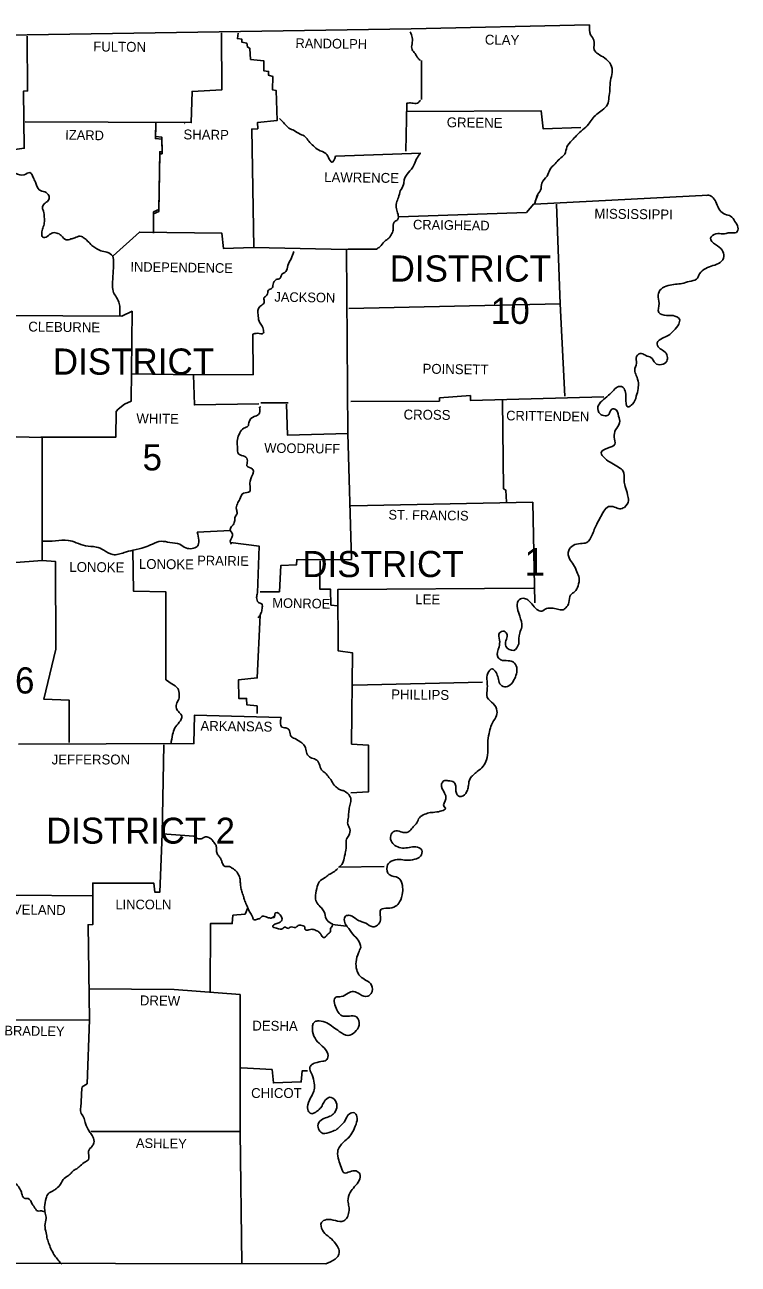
# Model space of a CAD drawing. Extents: x -17668 to 16999, y -17303 to 5867.
# Drawn here: x 2998 to 4708, y -10105 to -7133 of the extents above; entities that cross this region are included whole.
import ezdxf

# ---------------------------------------------------------------- set-up
doc = ezdxf.new("R2010")
doc.units = 0
for name, color, linetype in [('1', 7, 'Continuous'), ('2', 7, 'Continuous'), ('3', 7, 'Continuous')]:
    doc.layers.add(name, color=color, linetype=linetype)

msp = doc.modelspace()

# ---------------------------------------------------------------- linework, layer by layer
at = {"layer": '1'}
for p, q in [((4219.3, -7563.1), (4225.9, -7542.7)), ((4221, -7556.5), (4227.6, -7540.5)), ((3563.3, -8039.7), (3628.8, -8039.7)), ((3749.3, -9152.5), (3859.4, -9150.8))]:
    msp.add_line(p, q, dxfattribs=at)
for points in [[(1332.2, -7158.5), (2222.1, -7159.1), (3003, -7157.4), (3924.3, -7143.1), (4351.4, -7133.2)], [(3003, -7160.7), (3004.1, -7291.7), (2994.8, -7292.3), (2996.4, -7429.3), (2957.9, -7434.8), (2961.2, -7471.7), (2974.4, -7488.8), (2973.3, -7532.2), (2898.5, -7535), (2895.7, -7602.1), (2827.5, -7604.3), (2824.2, -7685.8), (2828, -7692.4), (2829.7, -7822.3), (2947.5, -7830), (2945.8, -8120), (3039.4, -8122.8), (3039.4, -8417.8), (2965.6, -8423.3), (2960.1, -8488.2), (2836.3, -8488.8)], [(3469.2, -7152.5), (3470.3, -7289), (3398.7, -7292.8), (3396.5, -7367.7), (2998.6, -7365.5)], [(3508.8, -7153), (3507.2, -7166.3), (3518.2, -7167.9), (3517.6, -7174.5), (3530.3, -7177.3), (3531.4, -7186.1), (3537.4, -7189.9), (3539.1, -7216.3), (3570.5, -7219.6), (3570.5, -7243.3), (3582, -7245), (3582, -7254.3), (3591.9, -7257.1), (3591.4, -7289), (3600.2, -7290.6), (3602.4, -7362.7), (3555.6, -7367.1), (3556.1, -7382.5), (3541.8, -7383.1), (3546.8, -7667.1), (3768.6, -7672), (3772.4, -8113.4), (3627.7, -8117.3), (3624.9, -8043)], [(3948.5, -7219.1), (3948.5, -7312.1)], [(3911.1, -7435.9), (3913.9, -7320.9), (3913.9, -7341.3), (4235.8, -7339.6), (4240.2, -7382.5), (4331, -7379.2)], [(3311.8, -7369.3), (3310.7, -7401.3), (3326.1, -7402.4), (3326.6, -7437.6), (3321.1, -7437.6), (3318.9, -7576.3), (3306.3, -7581.8), (3306.3, -7628)], [(3311.8, -7374.3), (3310.7, -7406.2), (3326.1, -7407.3), (3326.6, -7442.5), (3321.1, -7442.5), (3318.9, -7581.2), (3306.3, -7586.7), (3306.3, -7633)], [(3380.6, -7370.4), (3381.1, -7369.9)], [(3742.7, -7448), (3946.9, -7440.9)], [(4219.3, -7563.1), (4637, -7541.6)], [(3894.6, -7593.3), (4200.1, -7583.4), (4218.2, -7562.5)], [(4272.2, -7563.6), (4281.5, -7801.9), (4292.5, -8023.7)], [(3209.4, -7686.9), (3272.2, -7630.2), (3470.3, -7633), (3474.1, -7669.8), (3546.2, -7667.1)], [(3840.7, -7670.9), (3773.5, -7670.9), (3768.6, -7672)], [(4281.5, -7801.9), (3774.6, -7813.5)], [(2947.5, -7830), (3230.3, -7831.6), (3254.6, -7820.1), (3252.9, -8035.3), (3236.4, -8042.4), (3221.5, -8055.1), (3216.6, -8060), (3216, -8121.7), (3036.1, -8121.7)], [(3544, -7875.1), (3545.1, -7972), (3402, -7972.5), (3255.1, -7969.8)], [(3402, -7972.5), (3404.2, -8044.6), (3558.9, -8041.9)], [(3779, -8036.4), (3991.5, -8035.3), (3992, -8027.6), (4065.8, -8022.1), (4065.8, -8033.6), (4386.1, -8024.8)], [(3563.3, -8049), (3560.5, -8049.6)], [(4142.8, -8033.6), (4145.6, -8245.5), (4150.5, -8248.8), (4152.2, -8277.4)], [(3772.4, -8113.4), (3780.7, -8415), (3649.7, -8415.6), (3649.2, -8427.7), (3611.2, -8429.9), (3607.9, -8492.6), (3561.6, -8492.6)], [(3779, -8286.8), (4216, -8278)], [(4216, -8278), (4220.4, -8519)], [(3410.9, -8349.5), (3490.7, -8345.7)], [(3490.7, -8374.3), (3559.4, -8383.1), (3555.6, -8495.4)], [(3256.8, -8392.4), (3257.9, -8491), (3335.5, -8492.6), (3336, -8703.9)], [(3039.4, -8417.8), (3071.3, -8420), (3071.8, -8630.2), (3043.2, -8749.6), (3104.3, -8752.4), (3103.8, -8853.6)], [(3705.8, -8418.3), (3705.3, -8486.6), (3730.6, -8486.6), (3731.7, -8524.5), (3747.7, -8526.2)], [(3779, -8974.7), (3822, -8972), (3821.4, -8860.2), (3781.2, -8857.5), (3783.4, -8639), (3748.8, -8634), (3747.7, -8487.1), (4217.1, -8483.8)], [(3561.6, -8548.2), (3555, -8699), (3509.9, -8703.9), (3511, -8748.5), (3529.2, -8748), (3529.7, -8763.4), (3554.5, -8766.1), (3555, -8784.3)], [(3784.5, -8716.6), (4094.9, -8708.9)], [(3612.3, -8794.2), (3404.2, -8788.7), (3403.1, -8856.4), (2982.1, -8858)], [(3331, -8859.7), (3326.6, -9072.7), (3403.1, -9078.7)], [(3326.6, -9072.7), (3321.7, -9212.5), (3309, -9212.5), (3306.8, -9191), (3160.4, -9191), (3160.4, -9221.8)], [(2964.5, -9220.2), (3159.3, -9221.3)], [(3160.4, -9221.3), (3161, -9290.1), (3149.4, -9290.6), (3152.7, -9519)], [(3532.5, -9250.4), (3525.9, -9265.3), (3496.7, -9268.1), (3495.1, -9287.9), (3442.8, -9287.9), (3442.2, -9452.4)], [(3594.1, -9274.7), (3595.8, -9273), (3597.4, -9271.4), (3597.4, -9271.4)], [(3151.1, -9444.2), (3355.3, -9445.8), (3513.8, -9457.9)], [(3513.8, -9457.9), (3513.8, -9787), (3518.2, -10103.5)], [(2904, -9519.6), (3152.7, -9519)], [(3152.7, -9519), (3147.2, -9672), (3135.1, -9679.7)], [(1700.9, -9655), (1702, -10100.2), (3719, -10103.5)], [(3516.5, -9633.5), (3590.3, -9637.9), (3593.6, -9669.8), (3660.2, -9667.6), (3662.9, -9640.6), (3675.6, -9640.6)], [(3156, -9786.5), (3513.8, -9786.5)]]:
    msp.add_lwpolyline(points, dxfattribs=at)
for points in [[(3921.6, -7150.3), (3926.5, -7164.1), (3926, -7178.9), (3926, -7192.7), (3933.1, -7202), (3940.3, -7213.6), (3945.8, -7218.5)], [(4351.4, -7133.2), (4354.2, -7157.4), (4361.9, -7170.1), (4363, -7193.2), (4372.3, -7203.1), (4388.3, -7213), (4402.6, -7229), (4405.9, -7247.7), (4401.5, -7267), (4400.4, -7288.4), (4398.2, -7307.1), (4394.9, -7324.2), (4381.7, -7338), (4369, -7347.9), (4357.5, -7359.4), (4349.2, -7371.5), (4334.9, -7384.7), (4320.6, -7398.5), (4309, -7410.6), (4297.5, -7426), (4292, -7443.1), (4279.3, -7455.2), (4269.4, -7466.2), (4256.2, -7481.1), (4249.6, -7495.9), (4236.9, -7513), (4234.2, -7529.5), (4225.9, -7542.7), (4225.4, -7544.9)], [(3946.3, -7313.7), (3939.2, -7320.9), (3925.4, -7320.9), (3913.9, -7320.9)], [(3608.4, -7357.8), (3620.5, -7370.4), (3631, -7380.9), (3643.1, -7386.9), (3657.4, -7395.2), (3670.1, -7401.8), (3678.3, -7412.3), (3689.9, -7423.8), (3701.4, -7433.2), (3719.6, -7442), (3725.7, -7451.3), (3733.9, -7462.9), (3742.7, -7448)], [(3945.2, -7441.4), (3937, -7454.6), (3930.4, -7470), (3917.2, -7487.7), (3907.3, -7504.7), (3905.6, -7516.3), (3897.9, -7531.7), (3893.5, -7547.1), (3888.6, -7560.3), (3888.6, -7574.1), (3892.4, -7587.8), (3891.3, -7600.5), (3883.1, -7606.5), (3880.9, -7622.5), (3877.6, -7633.5), (3870.4, -7644.5), (3859.9, -7652.8), (3848.9, -7665.4), (3840.7, -7670.9)], [(2974.4, -7488.8), (2996.4, -7492.6), (3009.6, -7487.7), (3019, -7502), (3024, -7513), (3032.2, -7528.9), (3045.4, -7533.9), (3055.3, -7542.7), (3055.3, -7552.1), (3046.5, -7560.9), (3039.9, -7569.7), (3042.1, -7580.1), (3044.3, -7594.4), (3044.3, -7608.2), (3041, -7620.8), (3038.3, -7632.4), (3041, -7642.3), (3051.5, -7640.7), (3062.5, -7632.4), (3074, -7632.4), (3085, -7638.5), (3096.6, -7648.9), (3108.2, -7646.7), (3117.5, -7644), (3130.7, -7640.1), (3140.1, -7645.1), (3148.3, -7651.7), (3158.2, -7662.1), (3167.6, -7668.7), (3179.7, -7674.8), (3194.6, -7678.6), (3208.3, -7688), (3210.5, -7703.9), (3210, -7717.7), (3208.9, -7734.8), (3207.8, -7753.5), (3209.4, -7771.6), (3215.5, -7783.8), (3223.2, -7798.1), (3225.4, -7811.3), (3224.8, -7832.2)], [(4631, -7542.1), (4637, -7541.6), (4655.8, -7561.4), (4664, -7577.9), (4676.1, -7587.3), (4689.9, -7592.2), (4700.3, -7604.9), (4707.5, -7618.6), (4703.6, -7630.8), (4688.2, -7631.9), (4671.2, -7634.6), (4654.7, -7634.1), (4641.4, -7645.1), (4653.5, -7659.9), (4669.5, -7673.7), (4673.9, -7688.5), (4665.1, -7702.8), (4647.5, -7710.6), (4630.4, -7717.2), (4615, -7730.4), (4607.9, -7743), (4590.8, -7748.5), (4573.2, -7753.5), (4557.8, -7755.1), (4540.2, -7758.4), (4523.1, -7766.7), (4516, -7781), (4518.2, -7801.4), (4517.6, -7822.8), (4535.8, -7830), (4551.7, -7830.5), (4567.1, -7838.8), (4565.5, -7850.9), (4553.9, -7866.3), (4540.2, -7878.4), (4526.4, -7884.5), (4513.8, -7896), (4518.2, -7907.6), (4529.7, -7915.3), (4538, -7927.9), (4536.9, -7939.5), (4523.7, -7947.8), (4509.4, -7944.5), (4498.9, -7930.7), (4486.8, -7926.3), (4476.3, -7921.3), (4464.2, -7928.5), (4464.2, -7944.5), (4459.8, -7961.5), (4463.7, -7974.2), (4468.6, -7991.8), (4468.1, -8005), (4463.7, -8023.7), (4454.3, -8043), (4443.3, -8049), (4438.9, -8028.1), (4436.7, -8011), (4430.1, -8001.1), (4421.3, -8000.6), (4409.7, -8008.8), (4397.1, -8021.5), (4381.1, -8035.3), (4371.8, -8049), (4376.7, -8066.1), (4388.8, -8070.5), (4398.2, -8067.2), (4403.1, -8056.2), (4412.5, -8054.5), (4421.3, -8071.6)], [(3642.5, -7677), (3635.9, -7694), (3628.2, -7710.6), (3623.3, -7724.9), (3612.8, -7733.1), (3609.5, -7740.8), (3600.2, -7744.1), (3593, -7755.1), (3589.7, -7765), (3582, -7769.4), (3578.2, -7781.5), (3571, -7788.2), (3571.6, -7799.2), (3563.3, -7806.9), (3556.7, -7815.7), (3556.7, -7827.8), (3559.4, -7843.7), (3564.9, -7853.1), (3569.9, -7865.2), (3569.4, -7872.9), (3555.6, -7872.9), (3544, -7875.1)], [(3560.5, -8049.6), (3557.8, -8067.7), (3547.3, -8072.7), (3535.2, -8084.8), (3532.5, -8095.8), (3522.6, -8100.2), (3513.2, -8111.8), (3507.2, -8127.7), (3507.2, -8144.2), (3511, -8162.9), (3524.8, -8167.9), (3531.4, -8178.9), (3530.3, -8190.5), (3543.5, -8198.2), (3545.7, -8204.8), (3543.5, -8211.9), (3537.4, -8232.3), (3538, -8246), (3536.9, -8252.1), (3522, -8256), (3513.2, -8270.8), (3507.2, -8281.3), (3505, -8295), (3506.6, -8304.9), (3502.2, -8312.6), (3500.6, -8324.2), (3495.1, -8334.1), (3490.1, -8343.5), (3495.6, -8354.5), (3494, -8362.2), (3490.7, -8374.3), (3493.4, -8378.1)], [(4421.3, -8071.6), (4423.5, -8087.5), (4414.1, -8104.6), (4410.8, -8121.7), (4412.5, -8138.7), (4394.9, -8148.1), (4379.5, -8159.1), (4388.3, -8172.3), (4404.8, -8184.4), (4421.3, -8193.8), (4431.8, -8203.1), (4434.5, -8225.7), (4437.3, -8240), (4442.8, -8259.8), (4445, -8273.6), (4435.1, -8290.1), (4423.5, -8293.4), (4411.4, -8289.5), (4397.1, -8288.4), (4385.5, -8299.4), (4377.3, -8314.8), (4369, -8330.3), (4363, -8343.5), (4356.9, -8357.8), (4344.8, -8374.3), (4329.9, -8377), (4312.3, -8381.4), (4301.9, -8393.5), (4303.5, -8413.9), (4313.4, -8427.7), (4321.1, -8444.7), (4326.6, -8459.6), (4323.9, -8478.3), (4316.2, -8492.1), (4306.3, -8500.3), (4301.9, -8517.9), (4294.7, -8531.1), (4288.1, -8535.5), (4274.9, -8534.4), (4260.6, -8531.7), (4248.5, -8532.8), (4236.9, -8538.8), (4225.4, -8535), (4213.3, -8521.8), (4203.4, -8511.9), (4192.4, -8508), (4180.8, -8514.1), (4178.6, -8532.2), (4184.1, -8550.9), (4189.1, -8576.3), (4184.1, -8591.7), (4182.4, -8617)], [(3040.5, -8371.5), (3071.3, -8370.4), (3101.6, -8369.3), (3120.8, -8374.8), (3142.8, -8382), (3168.7, -8385.3), (3186.9, -8392.4), (3208.3, -8403.4), (3235.8, -8398.5), (3257.3, -8393), (3285.4, -8385.8), (3303.5, -8378.1), (3324.4, -8371.5), (3345.4, -8374.3), (3369, -8378.7), (3383.9, -8387.5), (3410.9, -8383.6), (3410.9, -8349.5)], [(3555.6, -8495.4), (3553.4, -8506.4), (3557.8, -8517.9), (3565.5, -8521.8), (3566.6, -8532.8), (3563.8, -8543.8), (3561.6, -8548.2), (3556.7, -8554.8)], [(4182.4, -8617), (4169.8, -8632.9), (4151.1, -8623), (4151.1, -8609.8), (4153.8, -8596.1), (4147.2, -8587.3), (4135.7, -8591.1), (4135.7, -8608.2), (4134.6, -8624.7), (4131.3, -8648.4), (4139, -8655.5), (4156.6, -8657.7), (4169.2, -8661), (4176.9, -8673.7), (4176.4, -8689.1), (4170.3, -8703.9), (4161.5, -8716), (4147.8, -8720.5), (4136.8, -8713.3), (4132.4, -8699), (4127.4, -8686.3), (4118.1, -8677), (4108.1, -8687.4), (4105.9, -8706.7), (4106.5, -8723.2), (4106.5, -8745.8), (4120.8, -8760.6), (4129.6, -8777.7), (4126.9, -8793.1), (4116.4, -8811.3), (4112, -8827.2), (4107.6, -8848.7), (4108.1, -8872.3), (4104.3, -8895.5), (4096.6, -8910.9), (4082.3, -8923.5), (4072.9, -8931.8), (4065.2, -8940), (4061.4, -8956.6), (4058.6, -8968.1), (4048.2, -8981.9), (4039.9, -8983), (4033.3, -8977.5), (4031.1, -8968.1), (4031.1, -8958.8), (4026.7, -8949.4), (4012.9, -8945.5), (4001.9, -8946.1), (3997, -8953.8), (4004.1, -8975.3), (4006.9, -8989), (4003, -9007.7), (4005.2, -9009.9), (3985.4, -9020.4), (3969.5, -9022), (3956.3, -9025.9), (3943.6, -9034.2), (3937.5, -9046.3), (3928.7, -9056.2), (3921, -9065.5), (3910.6, -9069.9), (3899, -9067.7), (3883.6, -9066.1), (3874.8, -9077.1), (3877.6, -9093), (3888, -9102.4), (3903.4, -9106.8), (3919.4, -9105.7), (3934.8, -9104), (3949.1, -9111.8), (3946.3, -9126.6), (3932.6, -9133.8), (3912.2, -9136), (3895.7, -9134.3), (3875.9, -9138.7), (3866, -9151.4), (3871.5, -9170.6), (3893, -9178.3), (3902.9, -9196.5), (3903.4, -9213.6), (3896.3, -9236.1), (3886.4, -9246.6), (3867.1, -9251), (3852.2, -9253.7), (3850, -9279.1), (3843.4, -9291.7), (3831.9, -9295.6), (3815.4, -9287.3), (3805.5, -9283.5), (3793.3, -9278), (3777.9, -9268.6), (3766.4, -9270.3), (3769.7, -9294.5), (3770.8, -9295.6), (3784, -9313.7), (3797.2, -9328), (3803.3, -9345.1)], [(3336, -8703.9), (3349.8, -8713.3), (3364.1, -8724.3), (3367.9, -8739.2), (3366.8, -8749.6), (3362.4, -8758.4), (3361.3, -8772.2), (3367.9, -8782.1), (3374, -8790.3), (3367.9, -8805.2), (3357.5, -8819), (3352, -8834.4), (3348.1, -8857.5)], [(3612.3, -8794.2), (3613.9, -8816.8), (3627.1, -8820.1), (3632.6, -8826.1), (3635.4, -8838.8), (3644.8, -8844.3), (3657.4, -8852), (3665.1, -8857.5), (3670.6, -8866.3), (3673.9, -8880.6), (3682.7, -8890), (3694.8, -8894.4), (3703.6, -8904.8), (3709.1, -8919.7), (3717.9, -8926.3), (3726.8, -8937.8), (3731.2, -8942.8), (3738.9, -8956), (3746.6, -8962.6), (3752.1, -8966.5), (3760.9, -8969.2), (3771.9, -8976.4), (3779, -8987.4), (3779, -8995.6), (3776.3, -9008.3), (3774.1, -9021.5), (3773, -9036.4), (3771.9, -9049.6), (3776.8, -9060.6), (3774.1, -9077.1), (3768.6, -9085.9), (3768, -9098), (3766.4, -9116.2), (3764.2, -9126.6), (3759.2, -9143.7), (3752.1, -9152.5)], [(3403.1, -9078.7), (3411.4, -9084.2), (3423, -9083.7), (3430.7, -9080.4), (3436.7, -9080.9), (3445, -9085.9), (3450.5, -9092.5), (3454.3, -9097.4), (3457.1, -9105.1), (3457.1, -9112.3), (3459.8, -9122.2), (3463.1, -9126.1), (3467.5, -9133.2), (3470.3, -9139.8), (3471.9, -9144.2), (3478, -9151.4), (3483.5, -9150.8), (3488.5, -9151.4), (3495.1, -9155.2), (3505, -9162.9), (3506.6, -9165.1), (3513.2, -9179.4), (3514.3, -9188.3), (3515.4, -9199.8), (3517.6, -9210.8), (3522, -9222.9), (3524.2, -9231.2), (3529.2, -9242.7), (3532.5, -9250.4), (3536.9, -9260.3), (3543.5, -9271.4), (3546.2, -9278), (3555.6, -9277.4), (3562.2, -9274.7), (3567.2, -9270.3), (3573.2, -9270.8), (3579.8, -9273), (3588.6, -9274.7), (3594.1, -9271.4), (3596.9, -9269.2), (3597.4, -9264.2), (3602.4, -9261.5), (3607.9, -9265.3), (3613.9, -9274.1), (3613.9, -9279.6), (3611.7, -9282.9), (3604.6, -9287.3), (3594.7, -9290.6), (3591.9, -9294.5), (3601.3, -9298.9), (3616.1, -9300), (3620, -9296.7), (3629.9, -9299.4), (3633.7, -9296.7), (3647, -9297.2), (3653, -9292.8), (3665.1, -9293.4), (3669, -9296.1), (3669, -9301.1), (3678.9, -9303.3), (3686, -9301.6), (3695.4, -9304.4), (3703.6, -9308.8), (3708, -9314.8), (3713.5, -9321.4), (3718.5, -9319.8), (3722.4, -9314.8), (3730.6, -9306), (3730.6, -9300.5), (3732.8, -9296.7), (3735.6, -9291.2)], [(3748.2, -9155.8), (3736.7, -9165.1), (3726.8, -9170.6), (3716.3, -9178.3), (3703.6, -9187.7), (3697.6, -9203.7), (3694.3, -9225.7), (3698.7, -9238.9), (3708.6, -9250.4), (3715.2, -9259.8), (3720.1, -9276.3), (3732.3, -9287.9), (3736.1, -9289.5)], [(3803.3, -9345.1), (3797.7, -9357.8), (3791.7, -9379.8), (3793.3, -9398.5), (3801.6, -9414.4), (3814.8, -9423.3), (3829.1, -9435.9), (3828, -9455.2), (3819.8, -9462.3), (3800.5, -9457.4), (3785.6, -9450.8), (3773, -9454.6), (3755.9, -9462.9), (3743.3, -9464.5), (3743.8, -9490.9), (3760.9, -9509.7), (3775.7, -9509.7), (3792.8, -9511.9), (3798.9, -9531.7), (3788.9, -9548.2), (3772.4, -9556.4), (3751.5, -9546.5), (3736.7, -9536.1), (3721.8, -9526.2), (3703.1, -9521.2), (3692.6, -9523.4), (3687.7, -9546.5), (3696.5, -9567.4), (3710.8, -9581.8), (3724, -9600.5), (3721.8, -9614.2), (3711.9, -9618.1), (3694.3, -9621.9), (3683.8, -9627.4), (3681.1, -9631.8), (3686.6, -9650.6), (3691.5, -9670.9), (3691.5, -9686.3), (3685.5, -9700.6), (3676.1, -9722.6), (3677.2, -9737), (3683.8, -9743.6), (3692.1, -9741.4), (3703.1, -9733.7), (3710.2, -9724.8), (3716.3, -9713.8), (3727.9, -9704.5), (3742.2, -9712.7), (3745.5, -9729.8), (3737.2, -9744.7), (3725.7, -9751.3), (3711.3, -9756.8), (3700.9, -9768.9), (3703.6, -9783.2), (3711.9, -9790.9), (3732.3, -9787), (3746, -9781), (3753.7, -9773.3), (3763.1, -9763.9), (3768, -9754.6), (3775.2, -9744.7), (3787.8, -9741.9), (3793.9, -9750.2), (3791.7, -9768.9), (3784, -9786.5), (3773.5, -9801.3), (3762, -9811.8), (3747.7, -9834.4), (3750.4, -9855.3), (3755.9, -9872.3), (3763.6, -9885.6), (3776.8, -9882.8), (3791.7, -9881.1), (3800.5, -9888.3), (3799.4, -9903.7), (3788.4, -9918.6), (3777.9, -9932.9), (3772.4, -9952.7), (3774.6, -9966.5), (3774.6, -9979.1), (3770.2, -9992.9), (3762.5, -10000.6), (3742.2, -10000), (3720.7, -9997.8), (3709.1, -10004.4), (3711.3, -10023.1), (3724, -10036.9), (3732.8, -10044.1), (3745.5, -10059.5), (3751, -10072.1), (3749.3, -10083.1), (3741.6, -10092.5), (3719, -10103.5)], [(3135.1, -9679.7), (3133.5, -9696.8), (3132.9, -9712.7), (3131.8, -9728.2), (3131.8, -9739.7), (3138.4, -9752.4), (3142.3, -9764.5), (3146.1, -9774.9), (3153.8, -9788.7), (3161, -9799.1), (3163.2, -9814), (3158.8, -9821.7), (3150.5, -9833.3), (3150, -9854.2), (3140.1, -9860.8), (3127.4, -9871.8), (3120.3, -9876.7), (3112.6, -9881.7), (3104.3, -9890.5), (3092.2, -9898.8), (3083.4, -9912.5), (3073.5, -9923), (3065.2, -9928.5), (3053.7, -9935.6), (3048.7, -9946.6), (3044.9, -9967), (3046.5, -9981.9), (3048.7, -9995.1), (3046, -10011.6), (3048.7, -10029.7), (3051.5, -10044.1), (3055.9, -10056.7), (3061.9, -10071), (3069.6, -10084.2), (3086.1, -10104.6)], [(2586.4, -9806.9), (2595.2, -9800.8), (2603.5, -9797.5), (2611.7, -9799.1), (2620.5, -9800.2), (2628.2, -9799.1), (2638.2, -9800.8), (2646.4, -9805.8), (2655.8, -9809.6), (2665.1, -9809.6), (2673.4, -9809.6), (2680.5, -9814.6), (2693.7, -9814), (2704.7, -9809.6), (2715.8, -9806.3), (2730.6, -9804.6), (2743.8, -9814), (2753.2, -9821.7), (2760.9, -9830.5), (2766.4, -9840.4), (2772.4, -9845.9), (2782.3, -9849.8), (2790.1, -9851.4), (2799.4, -9854.2), (2804.4, -9856.4), (2808.8, -9866.8), (2815.9, -9881.1), (2829.7, -9886.1), (2846.7, -9879.5), (2860.5, -9875.6), (2870.4, -9872.3), (2876.5, -9870.1), (2882, -9869.6), (2880.3, -9868.5), (2886.9, -9866.8), (2893, -9871.2), (2896.8, -9877.3), (2903.4, -9886.1), (2909.5, -9893.8), (2915.5, -9896.6), (2921.6, -9893.3), (2929.8, -9896), (2937, -9898.8), (2945.3, -9901), (2952.4, -9901.5), (2961.8, -9903.7), (2968.9, -9907.6), (2975.5, -9911.4), (2982.1, -9918.6), (2988.7, -9929.6), (2990.9, -9938.4), (2998.6, -9947.2), (3005.8, -9947.2), (3016.2, -9961.5), (3020.1, -9967), (3028.4, -9976.9), (3034.4, -9976.9), (3046, -9979.1)]]:
    msp.add_spline(points, degree=3, dxfattribs=at)
at = {"layer": '3'}
msp.add_line((3734.5, -9290.1), (3769.1, -9294.5), dxfattribs=at)

# ---------------------------------------------------------------- texts
at = {"layer": '1'}
msp.add_text('1', height=66, dxfattribs=at).set_placement((4195.7, -8453.5))
at = {"layer": '2'}
for s, height, rotation, p in [('CLAY', 23.66, 359.2258, (4100.4, -7180.6)), ('FULTON', 23.66, 359.4996, (3161.5, -7197.1)), ('RANDOLPH', 23.11, 359.2583, (3646.4, -7188.8)), ('GREENE', 23.67, 359.2361, (4009.1, -7378.7)), ('IZARD', 23.11, 358.9258, (3094.4, -7408.4)), ('SHARP', 23.66, 359.3905, (3377.8, -7407.9)), ('LAWRENCE', 23.67, 359.2678, (3715.2, -7510.2)), ('MISSISSIPPI', 23.66, 359.3097, (4363, -7597.7)), ('CRAIGHEAD', 23.11, 359.1159, (3928.2, -7623.6)), ('INDEPENDENCE', 23.108, 359.2187, (3250.7, -7724.9)), ('JACKSON', 23.11, 359.1352, (3595.8, -7797)), ('CLEBURNE', 23.66, 359.2535, (3005.8, -7868.5)), ('POINSETT', 23.66, 359.1987, (3951.1, -7969.5)), ('WHITE', 23.67, 359.3139, (3265, -8088.6)), ('CROSS', 23.66, 359.3839, (3905.6, -8079.3)), ('CRITTENDEN', 23.11, 359.213, (4151.6, -8081.5)), ('WOODRUFF', 23.11, 359.2748, (3571.6, -8159.1)), ('ST. FRANCIS', 23.108, 359.2216, (3869.3, -8319.2)), ('PRAIRIE', 23.11, 359.2116, (3410.9, -8428.8)), ('LONOKE', 23.67, 359.4974, (3104.3, -8444.7)), ('LONOKE', 23.67, 359.4974, (3271.1, -8437.6)), ('MONROE', 23.11, 359.0331, (3590.8, -8530.6)), ('LEE', 23.67, 359.4327, (3933.7, -8522.3)), ('PHILLIPS', 23.66, 359.3179, (3875.9, -8750.2)), ('ARKANSAS', 23.66, 359.2678, (3418.6, -8825.6)), ('CLEVELAND', 23.67, 359.3377, (2907.3, -9265.3)), ('DREW', 23.66, 359.2258, (3273.3, -9483.8)), ('BRADLEY', 23.11, 359.1449, (2948.6, -9555.9)), ('DESHA', 23.66, 359.3704, (3542.9, -9544.3)), ('ASHLEY', 23.11, 359.2361, (3263.9, -9825.6))]:
    msp.add_text(s, height=height, rotation=rotation, dxfattribs=at).set_placement(p)
for s, height, p in [('JEFFERSON', 23.67, (3061.9, -8906.5)), ('LINCOLN', 23.11, (3214.9, -9253.7)), ('CHICOT', 23.67, (3540.2, -9706.1))]:
    msp.add_text(s, height=height, dxfattribs=at).set_placement(p)
at = {"layer": '3'}
for s, height, p in [('DISTRICT', 62.74, (3872.3, -7748.9)), ('10', 62.74, (4114.8, -7850.4)), ('DISTRICT', 62.74, (3064.7, -7972)), ('5', 62.7, (3279.9, -8201.5)), ('DISTRICT', 62.74, (3662.9, -8457.4)), ('DISTRICT 6', 62.74, (2563.9, -8736.4)), ('DISTRICT 2', 62.19, (3048.7, -9096.3))]:
    msp.add_text(s, height=height, dxfattribs=at).set_placement(p)

doc.saveas('drawing.dxf')
